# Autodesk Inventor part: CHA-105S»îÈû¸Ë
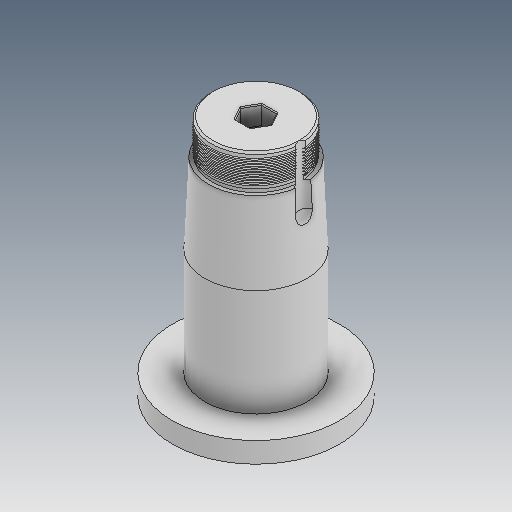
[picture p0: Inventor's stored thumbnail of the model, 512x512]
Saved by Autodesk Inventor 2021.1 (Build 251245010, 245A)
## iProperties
Created: 2019-12
Part Number: CHA-105S»îÈû¸Ë
Material: Ogólny
Document SubType Name: Modeling
Designer: user
Density: 1 g/cm^3
Appearance: Domyślna
Author: user
Revision Number: ÈÎºÎ
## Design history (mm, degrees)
feature "ÊäÈë1"
node "Bryła1"
